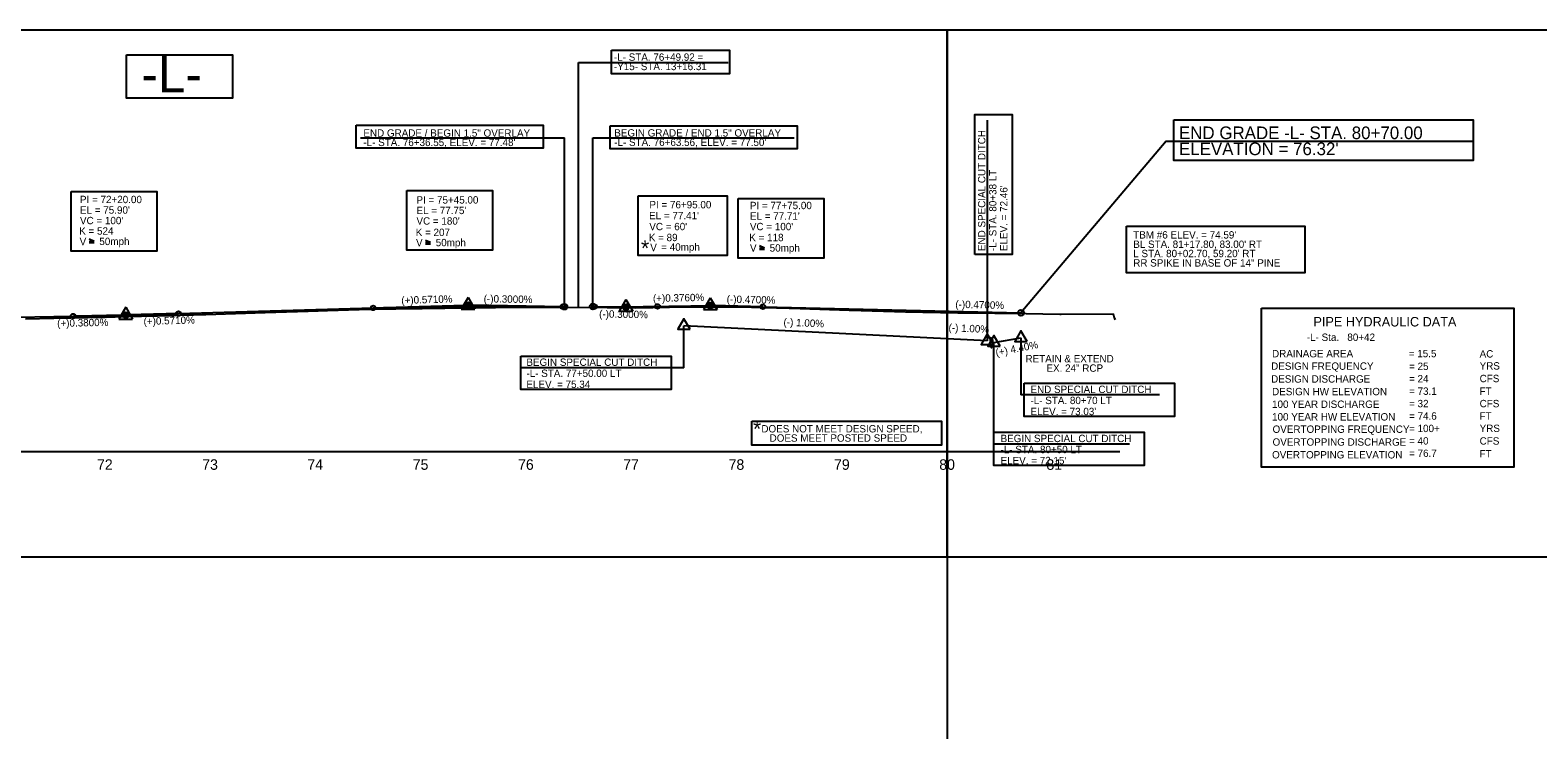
# Model space of a CAD drawing. Extents: x 2366464 to 2375718, y 801842 to 804354.
# Drawn here: x 2373447 to 2374879, y 803581 to 804254 of the extents above; entities that cross this region are included whole.
import ezdxf

# ---------------------------------------------------------------- set-up
doc = ezdxf.new("R2010")
doc.units = 0
for name, color, linetype in [('Default', 7, 'Continuous'), ('Exist Profile Cell', 7, 'Continuous'), ('Exist Vertical Profile Ground Line', 7, 'Continuous'), ('Exist Vertical Profile Horizontal Axis Label Major', 7, 'Continuous'), ('Prop Grid Mask', 7, 'Continuous'), ('Prop PFL VPI Symbol CELL', 7, 'Continuous'), ('Prop Vertical Profile Curve Label', 7, 'Continuous'), ('Prop Vertical Profile Ditch Grade Left', 7, 'Continuous'), ('Prop Vertical Profile Ditch Grade Left Label', 7, 'Continuous'), ('Prop Vertical Profile Grade', 7, 'Continuous'), ('Prop Vertical Profile Grade Label', 7, 'Continuous'), ('Prop VPI Label', 7, 'Continuous'), ('Scratch_Level_5', 7, 'Continuous'), ('Sheet Layout Profile Border Port 1', 7, 'Continuous'), ('Sheet Layout Profile Border Port 2', 7, 'Continuous')]:
    doc.layers.add(name, color=color, linetype=linetype)

# ---------------------------------------------------------------- blocks, each defined once
blk = doc.blocks.new('Profile VPI Symbol')
at = {"layer": 'Prop PFL VPI Symbol CELL'}
for p, q in [((-0.001, 0.147), (-0.13, -0.077)), ((-0.001, 0.147), (0.129, -0.077)), ((-0.13, -0.077), (0.129, -0.077))]:
    blk.add_line(p, q, dxfattribs=at)
for radius in [0.035, 0.024]:
    blk.add_circle((-0.001, -0.003), radius, dxfattribs=at)

msp = doc.modelspace()

# ---------------------------------------------------------------- linework, layer by layer
at = {"layer": 'Default'}
msp.add_line((2374318, 803754), (2374318, 803581), dxfattribs=at)
msp.add_ellipse((2374360, 803957.4), major_axis=(0, 5), ratio=0.2, dxfattribs=at)
at = {"layer": 'Exist Profile Cell'}
msp.add_line((2367318, 803854), (2374481.8, 803854), dxfattribs=at)
at = {"layer": 'Exist Vertical Profile Ground Line'}
msp.add_lwpolyline([(2373442.8, 803980), (2373469.6, 803980.6), (2373518.1, 803981.6), (2373537.6, 803982), (2373552.9, 803982.4), (2373563.2, 803982.6), (2373568.2, 803982.7), (2373583.5, 803983.1), (2373589.9, 803983.3), (2373598.8, 803983.6), (2373602.4, 803983.7), (2373610.6, 803983.9), (2373614.1, 803984.1), (2373670.3, 803986), (2373711.2, 803987.3), (2373720.8, 803987.6), (2373729.4, 803987.8), (2373769.7, 803988.9), (2373770.7, 803988.9), (2373818.3, 803989.8), (2373819.4, 803989.8), (2373862.9, 803990.4), (2373863.9, 803990.4), (2373914, 803991), (2373956.6, 803990.7), (2373967.9, 803991.1), (2374022.4, 803990.4), (2374070.4, 803991.3), (2374071.6, 803991.3), (2374119.1, 803991.2), (2374120.1, 803991.2), (2374167.9, 803990.1), (2374168.4, 803990.1), (2374168.9, 803990.1), (2374225, 803988), (2374225.9, 803988), (2374278.3, 803986.4), (2374327.9, 803985.7), (2374363.2, 803985.3), (2374364.5, 803985.3), (2374375.4, 803985.1), (2374376.7, 803985.1), (2374424.8, 803984.3), (2374426.2, 803984.3), (2374475.6, 803984.5), (2374476.6, 803980.9), (2374477.3, 803979.1)], dxfattribs=at)
at = {"layer": 'Prop Grid Mask'}
for points in [[(2373538.7, 804230.7), (2373639.4, 804230.7), (2373639.4, 804189.4), (2373538.7, 804189.4)], [(2373999.2, 804235.1), (2374111.3, 804235.1), (2374111.3, 804212.5), (2373999.2, 804212.5)], [(2374344.2, 804040.8), (2374344.2, 804173.9), (2374379.6, 804173.9), (2374379.6, 804040.8)], [(2373756.8, 804163.7), (2373934.2, 804163.7), (2373934.2, 804141.8), (2373756.8, 804141.8)], [(2373998, 804163.1), (2374175.4, 804163.1), (2374175.4, 804141.2), (2373998, 804141.2)], [(2374533, 804168.8), (2374817.4, 804168.8), (2374817.4, 804130.2), (2374533, 804130.2)], [(2373805, 804101.7), (2373886.3, 804101.7), (2373886.3, 804045), (2373805, 804045)], [(2373486.2, 804100.7), (2373567.5, 804100.7), (2373567.5, 804044), (2373486.2, 804044)], [(2374024.5, 804096.7), (2374109.1, 804096.7), (2374109.1, 804039.9), (2374024.5, 804039.9)], [(2374119.6, 804094.2), (2374200.9, 804094.2), (2374200.9, 804037.5), (2374119.6, 804037.5)], [(2374488.1, 804067.7), (2374657.6, 804067.7), (2374657.6, 804023.5), (2374488.1, 804023.5)], [(2374616.5, 803990.1), (2374856.1, 803990.1), (2374856.1, 803839.1), (2374616.5, 803839.1)], [(2373913, 803944.5), (2374055.9, 803944.5), (2374055.9, 803912.7), (2373913, 803912.7)], [(2374391, 803918.8), (2374533.8, 803918.8), (2374533.8, 803887), (2374391, 803887)], [(2374132.3, 803882.6), (2374312.5, 803882.6), (2374312.5, 803859.8), (2374132.3, 803859.8)], [(2374362.1, 803872.3), (2374504.9, 803872.3), (2374504.9, 803840.6), (2374362.1, 803840.6)]]:
    msp.add_lwpolyline(points, close=True, dxfattribs=at)
at = {"layer": 'Prop Vertical Profile Curve Label'}
for p, q in [((2373967.9, 803991.1), (2373967.9, 804223.4)), ((2373507.9, 804053.4), (2373503.2, 804055.4)), ((2373503.2, 804053.4), (2373507.9, 804053.4)), ((2373503.2, 804052.3), (2373507.9, 804052.3)), ((2373822.6, 804052.3), (2373827.3, 804052.3)), ((2373822.6, 804051.2), (2373827.3, 804051.2)), ((2373827.3, 804052.3), (2373822.7, 804054.3)), ((2374139.7, 804047.1), (2374144.4, 804047.1)), ((2374139.7, 804046.1), (2374144.4, 804046.1)), ((2374144.4, 804047.1), (2374139.8, 804049.1))]:
    msp.add_line(p, q, dxfattribs=at)
for centre in [(2373588, 803984.9), (2373773, 803990.2), (2373953, 803991.4), (2373983, 803991.5), (2374043, 803991.6), (2374043, 803991.6), (2374143, 803991.3), (2373488, 803982.5)]:
    msp.add_circle(centre, 2.25, dxfattribs=at)
at = {"layer": 'Prop Vertical Profile Ditch Grade Left'}
for p, q in [((2374318, 803960.8), (2374068, 803973.3)), ((2374356, 803958.9), (2374318, 803960.8)), ((2374356, 803960.8), (2374356, 803958.9)), ((2374362.3, 803957.3), (2374388, 803961.7))]:
    msp.add_line(p, q, dxfattribs=at)
at = {"layer": 'Prop Vertical Profile Ditch Grade Left Label'}
for p, q in [((2374356, 804168.5), (2374356, 803958.9)), ((2374356, 804168.5), (2374356, 803958.9)), ((2374356, 804071), (2374356, 803958.9)), ((2374068, 803933.3), (2374068, 803973.3)), ((2374388, 803961.7), (2374388, 803907.6)), ((2374362.3, 803860.9), (2374362.3, 803957.3)), ((2374068, 803933.3), (2373913, 803933.3)), ((2374519.6, 803907.6), (2374388, 803907.6)), ((2374491.1, 803860.9), (2374362.3, 803860.9))]:
    msp.add_line(p, q, dxfattribs=at)
for points in [[(2374073.8, 803969.9), (2374068, 803980), (2374062.1, 803969.9)], [(2374361.8, 803955.5), (2374356, 803965.6), (2374350.1, 803955.5)], [(2374368.1, 803954), (2374362.3, 803964.1), (2374356.4, 803954)], [(2374393.8, 803958.4), (2374388, 803968.5), (2374382.1, 803958.4)]]:
    msp.add_lwpolyline(points, close=True, dxfattribs=at)
at = {"layer": 'Prop Vertical Profile Grade'}
for p, q in [((2373588, 803984.9), (2373773, 803990.2)), ((2373953, 803991.4), (2373954.5, 803991.4)), ((2373981.5, 803991.5), (2373983, 803991.5)), ((2374143, 803991.3), (2374388, 803985.6)), ((2373408, 803981), (2373488, 803982.5))]:
    msp.add_line(p, q, dxfattribs=at)
for points in [[(2373773, 803990.2), (2373776.6, 803990.3), (2373780.2, 803990.4), (2373783.8, 803990.5), (2373787.4, 803990.6), (2373791, 803990.7), (2373794.6, 803990.7), (2373798.2, 803990.8), (2373801.8, 803990.9), (2373805.4, 803991), (2373809, 803991.1), (2373812.6, 803991.1), (2373816.2, 803991.2), (2373819.8, 803991.3), (2373823.4, 803991.3), (2373827, 803991.4), (2373830.6, 803991.4), (2373834.2, 803991.5), (2373837.8, 803991.5), (2373841.4, 803991.6), (2373845, 803991.6), (2373848.6, 803991.7), (2373852.2, 803991.7), (2373855.8, 803991.7), (2373859.4, 803991.8), (2373863, 803991.8), (2373866.6, 803991.8), (2373870.2, 803991.8), (2373873.8, 803991.8), (2373877.4, 803991.8), (2373881, 803991.9), (2373884.6, 803991.9), (2373888.2, 803991.9), (2373891.8, 803991.9), (2373895.4, 803991.9), (2373899, 803991.9), (2373902.6, 803991.9), (2373906.2, 803991.8), (2373909.8, 803991.8), (2373913.4, 803991.8), (2373917, 803991.8), (2373920.6, 803991.8), (2373924.2, 803991.7), (2373927.8, 803991.7), (2373931.4, 803991.7), (2373935, 803991.6), (2373938.6, 803991.6), (2373942.2, 803991.6), (2373945.8, 803991.5), (2373949.4, 803991.5), (2373953, 803991.4)], [(2373983, 803991.5), (2373984.2, 803991.4), (2373985.4, 803991.4), (2373986.6, 803991.4), (2373987.8, 803991.4), (2373989, 803991.4), (2373990.2, 803991.4), (2373991.4, 803991.4), (2373992.6, 803991.3), (2373993.8, 803991.3), (2373995, 803991.3), (2373996.2, 803991.3), (2373997.4, 803991.3), (2373998.6, 803991.3), (2373999.8, 803991.3), (2374001, 803991.3), (2374002.2, 803991.3), (2374003.4, 803991.3), (2374004.6, 803991.3), (2374005.8, 803991.3), (2374007, 803991.3), (2374008.2, 803991.3), (2374009.4, 803991.3), (2374010.6, 803991.3), (2374011.8, 803991.3), (2374013, 803991.3), (2374014.2, 803991.3), (2374015.4, 803991.3), (2374016.6, 803991.3), (2374017.8, 803991.3), (2374019, 803991.3), (2374020.2, 803991.3), (2374021.4, 803991.3), (2374022.6, 803991.3), (2374023.8, 803991.3), (2374025, 803991.3), (2374026.2, 803991.3), (2374027.4, 803991.4), (2374028.6, 803991.4), (2374029.8, 803991.4), (2374031, 803991.4), (2374032.2, 803991.4), (2374033.4, 803991.4), (2374034.6, 803991.4), (2374035.8, 803991.5), (2374037, 803991.5), (2374038.2, 803991.5), (2374039.4, 803991.5), (2374040.6, 803991.5), (2374041.8, 803991.6), (2374043, 803991.6)], [(2374043, 803991.6), (2374045, 803991.6), (2374047, 803991.6), (2374049, 803991.7), (2374051, 803991.7), (2374053, 803991.7), (2374055, 803991.8), (2374057, 803991.8), (2374059, 803991.8), (2374061, 803991.8), (2374063, 803991.9), (2374065, 803991.9), (2374067, 803991.9), (2374069, 803991.9), (2374071, 803991.9), (2374073, 803991.9), (2374075, 803992), (2374077, 803992), (2374079, 803992), (2374081, 803992), (2374083, 803992), (2374085, 803992), (2374087, 803992), (2374089, 803992), (2374091, 803992), (2374093, 803992), (2374095, 803992), (2374097, 803992), (2374099, 803992), (2374101, 803992), (2374103, 803991.9), (2374105, 803991.9), (2374107, 803991.9), (2374109, 803991.9), (2374111, 803991.9), (2374113, 803991.9), (2374115, 803991.8), (2374117, 803991.8), (2374119, 803991.8), (2374121, 803991.8), (2374123, 803991.7), (2374125, 803991.7), (2374127, 803991.7), (2374129, 803991.6), (2374131, 803991.6), (2374133, 803991.6), (2374135, 803991.5), (2374137, 803991.5), (2374139, 803991.4), (2374141, 803991.4), (2374143, 803991.3)], [(2373488, 803982.5), (2373490, 803982.6), (2373492, 803982.6), (2373494, 803982.6), (2373496, 803982.7), (2373498, 803982.7), (2373500, 803982.8), (2373502, 803982.8), (2373504, 803982.8), (2373506, 803982.9), (2373508, 803982.9), (2373510, 803983), (2373512, 803983), (2373514, 803983.1), (2373516, 803983.1), (2373518, 803983.1), (2373520, 803983.2), (2373522, 803983.2), (2373524, 803983.3), (2373526, 803983.3), (2373528, 803983.4), (2373530, 803983.4), (2373532, 803983.5), (2373534, 803983.5), (2373536, 803983.6), (2373538, 803983.6), (2373540, 803983.6), (2373542, 803983.7), (2373544, 803983.7), (2373546, 803983.8), (2373548, 803983.8), (2373550, 803983.9), (2373552, 803983.9), (2373554, 803984), (2373556, 803984), (2373558, 803984.1), (2373560, 803984.1), (2373562, 803984.2), (2373564, 803984.2), (2373566, 803984.3), (2373568, 803984.4), (2373570, 803984.4), (2373572, 803984.5), (2373574, 803984.5), (2373576, 803984.6), (2373578, 803984.6), (2373580, 803984.7), (2373582, 803984.7), (2373584, 803984.8), (2373586, 803984.8), (2373588, 803984.9)]]:
    msp.add_spline(points, degree=3, dxfattribs=at)
at = {"layer": 'Prop VPI Label'}
for p, q in [((2373967.9, 804223.4), (2374109.9, 804223.4)), ((2373760.9, 804151.7), (2373954.5, 804151.7)), ((2373954.5, 803991.4), (2373954.5, 804151.7)), ((2373981.5, 803991.5), (2373981.5, 804151.7)), ((2373981.5, 804151.7), (2374172.6, 804151.7)), ((2374526, 804148.5), (2374388, 803985.6)), ((2374526, 804148.5), (2374816.8, 804148.5)), ((2373773, 803990.2), (2373860.2, 803992.7)), ((2373953, 803991.4), (2373865.7, 803992.7)), ((2373983, 803991.5), (2374010.2, 803991.1)), ((2374043, 803991.6), (2374015.7, 803991.1)), ((2374043, 803991.6), (2374090.2, 803992.5)), ((2374143, 803991.3), (2374095.7, 803992.5)), ((2373488, 803982.5), (2373535.2, 803983.4)), ((2373588, 803984.9), (2373540.7, 803983.6))]:
    msp.add_line(p, q, dxfattribs=at)
for centre in [(2373863, 803992.8), (2373954.5, 803991.4), (2373981.5, 803991.5), (2374013, 803991), (2374093, 803992.5), (2374388, 803985.6), (2374388, 803985.6), (2373538, 803983.5)]:
    msp.add_circle(centre, 2.75, dxfattribs=at)
at = {"layer": 'Scratch_Level_5'}
for p, q in [((2373718, 803988.6), (2373718, 803988.6)), ((2373768, 803989.4), (2373768, 803989.4)), ((2373834, 803990.7), (2373834, 803990.7)), ((2373918, 803991.7), (2373918, 803991.7)), ((2373918, 803991.7), (2373918, 803991.7)), ((2373954.5, 803991.4), (2373954.5, 803991.4)), ((2373981.5, 803991.5), (2373981.5, 803991.5)), ((2374068, 803991.9), (2374068, 803991.9)), ((2374168, 803990.7), (2374168, 803990.7)), ((2374268, 803987.7), (2374268, 803987.7)), ((2373468, 803981.2), (2373468, 803981.2)), ((2373518, 803982.2), (2373518, 803982.2)), ((2373579, 803984), (2373579, 803984)), ((2373637, 803985.2), (2373637, 803985.2)), ((2374368, 803985.9), (2374368, 803985.9))]:
    msp.add_line(p, q, dxfattribs=at)
at = {"layer": 'Sheet Layout Profile Border Port 1'}
msp.add_lwpolyline([(2372918, 803754), (2374318, 803754), (2374318, 804254), (2372918, 804254)], close=True, dxfattribs=at)
at = {"layer": 'Sheet Layout Profile Border Port 2'}
msp.add_lwpolyline([(2374318, 803754), (2375718, 803754), (2375718, 804254), (2374318, 804254)], close=True, dxfattribs=at)

# ---------------------------------------------------------------- block references
at = {"layer": 'Prop Grid Mask', "xscale": 50, "yscale": 50}
for p in [(2373538, 803983.5), (2373863, 803992.8), (2374013, 803991), (2374093, 803992.5)]:
    msp.add_blockref('Profile VPI Symbol', p, dxfattribs=at)

# ---------------------------------------------------------------- texts
at = {"layer": 'Default'}
for s, p in [('RETAIN & EXTEND', (2374392.3, 803938.5)), ('EX. 24" RCP', (2374412.2, 803929.6))]:
    msp.add_text(s, height=7, dxfattribs=at).set_placement(p)
at = {"layer": 'Exist Vertical Profile Horizontal Axis Label Major'}
for s, p in [('72', (2373510.7, 803836.5)), ('73', (2373610.6, 803836.5)), ('74', (2373710.4, 803836.5)), ('75', (2373810.5, 803836.5)), ('76', (2373910.5, 803836.5)), ('77', (2374010.3, 803836.5)), ('78', (2374110.4, 803836.5)), ('79', (2374210.5, 803836.5)), ('80', (2374310.4, 803836.5)), ('81', (2374412.2, 803836.5))]:
    msp.add_text(s, height=10, dxfattribs=at).set_placement(p)
at = {"layer": 'Prop Vertical Profile Curve Label'}
for s, height, p in [('-L- STA. 76+49.92 = ', 7, (2374001.5, 804224.9)), ('-Y15- STA. 13+16.31', 7, (2374001.5, 804216)), ("VC = 100'", 7, (2373494.5, 804069.7)), ("VC = 180'", 7, (2373814, 804069.3)), ('K = 524', 7, (2373493.8, 804059.8)), ('K = 207', 7, (2373813.3, 804058.5)), ("VC = 60'", 7, (2374035.1, 804064)), ('K = 89', 7, (2374034.6, 804053.6)), ("VC = 100'", 7, (2374130.6, 804064)), ('K = 118', 7, (2374130, 804053.6)), ('V', 7, (2373494.2, 804049.8)), ('50mph', 7, (2373512.9, 804049.9)), ('V', 7, (2373813.6, 804048.7)), ('50mph', 7, (2373832.3, 804048.8)), ('*', 15, (2374027.2, 804039.5)), ('V', 7, (2374036, 804044.1)), ('= 40mph', 7, (2374046.4, 804044.5)), ('V', 7, (2374130.7, 804043.6)), ('50mph', 7, (2374149.4, 804043.7)), ('*', 15, (2374133.6, 803867.9)), ('DOES NOT MEET DESIGN SPEED, ', 7, (2374141.5, 803872)), ('   DOES MEET POSTED SPEED', 7, (2374141.5, 803863.2))]:
    msp.add_text(s, height=height, dxfattribs=at).set_placement(p)
at = {"layer": 'Prop Vertical Profile Ditch Grade Left Label'}
for s, rotation, p in [('END SPECIAL CUT DITCH', 90, (2374354.2, 804044.2)), ('-L- STA. 80+38 LT', 90, (2374364.7, 804044.2)), ("ELEV. = 72.46'", 90, (2374375.2, 804044.2)), ('(-) 1.00%', 357.2828, (2374162.4, 803973.5)), ('(-) 1.00%', 357.2828, (2374319.1, 803968.2)), ('(+) 4.40%', 11.1463, (2374364.6, 803944.3))]:
    msp.add_text(s, height=7, rotation=rotation, dxfattribs=at).set_placement(p)
for s, height, p in [('PIPE HYDRAULIC DATA', 9, (2374665.7, 803972.6)), ('-L- Sta.   80+42', 7, (2374659.4, 803958.9)), ('DRAINAGE AREA', 7, (2374626.4, 803943.3)), ('= 15.5', 7, (2374756.2, 803943.4)), ('AC', 7, (2374823.5, 803943.1)), ('-L- STA. 77+50.00 LT', 7, (2373918.4, 803924.7)), ('BEGIN SPECIAL CUT DITCH', 7, (2373918.4, 803935.2)), ('DESIGN FREQUENCY', 7, (2374625.5, 803931.5)), ('= 25', 7, (2374756.5, 803931.3)), ('YRS', 7, (2374823.5, 803931.7)), ('ELEV. = 75.34', 7, (2373918.4, 803914.2)), ('END SPECIAL CUT DITCH', 7, (2374397, 803909.4)), ('DESIGN DISCHARGE', 7, (2374625.5, 803919.3)), ('= 24', 7, (2374756.5, 803919.5)), ('CFS', 7, (2374823.5, 803919.7)), ('-L- STA. 80+70 LT', 7, (2374397, 803898.9)), ('DESIGN HW ELEVATION', 7, (2374626.4, 803907.3)), ('100 YEAR DISCHARGE', 7, (2374626.4, 803895.3)), ('= 73.1', 7, (2374756.5, 803907.7)), ('= 32', 7, (2374756.5, 803895.9)), ('CFS', 7, (2374823.5, 803895.9)), ('FT', 7, (2374823.5, 803907.7)), ("ELEV. = 73.03'", 7, (2374397, 803888.4)), ('100 YEAR HW ELEVATION', 7, (2374626.4, 803883.3)), ('= 74.6', 7, (2374756.5, 803884.1)), ('FT', 7, (2374823.5, 803884.1)), ('OVERTOPPING FREQUENCY', 7, (2374626.9, 803871.6)), ('= 100+', 7, (2374756.5, 803872.3)), ('YRS', 7, (2374823.5, 803872.4)), ('-L- STA. 80+50 LT', 7, (2374368.6, 803852.3)), ('BEGIN SPECIAL CUT DITCH', 7, (2374368.6, 803862.8)), ('OVERTOPPING DISCHARGE', 7, (2374626.9, 803859.4)), ('= 40', 7, (2374756.5, 803860.5)), ('CFS', 7, (2374823.5, 803860.4)), ("ELEV. = 72.15'", 7, (2374368.6, 803841.8)), ('OVERTOPPING ELEVATION', 7, (2374626.4, 803847.3)), ('= 76.7', 7, (2374756.5, 803848.7)), ('FT', 7, (2374823.5, 803848.3))]:
    msp.add_text(s, height=height, dxfattribs=at).set_placement(p)
at = {"layer": 'Prop Vertical Profile Grade Label'}
for s, rotation, p in [('(+)0.5710%', 1.6353, (2373799.7, 803994)), ('(-)0.3000%', 359.1406, (2373877.8, 803995.5)), ('(+)0.3760%', 1.0771, (2374038.6, 803995.9)), ('(-)0.4700%', 358.6538, (2374108.5, 803995.2)), ('(-)0.3000%', 359.1406, (2373987.4, 803981.1)), ('(-)0.4700%', 358.6538, (2374325.6, 803990.3)), ('(+)0.3800%', 1.0885, (2373472.9, 803972.2)), ('(+)0.5710%', 1.6353, (2373555, 803974))]:
    msp.add_text(s, height=7, rotation=rotation, dxfattribs=at).set_placement(p)
at = {"layer": 'Prop VPI Label'}
for s, height, p in [('-L-', 35, (2373553, 804194.8)), ('BEGIN GRADE / END 1.5" OVERLAY', 7, (2374001.8, 804152.9)), ('END GRADE -L- STA. 80+70.00', 12, (2374538, 804150.5)), ("-L- STA. 76+63.56, ELEV. = 77.50'", 7, (2374001.8, 804144)), ("ELEVATION = 76.32'", 12, (2374538, 804135.3)), ('PI = 72+20.00', 7, (2373494.5, 804089.7)), ('PI = 75+45.00', 7, (2373814, 804089.3)), ('PI = 76+95.00', 7, (2374035.2, 804084.8)), ('PI = 77+75.00', 7, (2374130.6, 804084)), ("EL = 75.90'", 7, (2373494.5, 804079.7)), ("EL = 77.75'", 7, (2373814, 804079.3)), ("EL = 77.41'", 7, (2374034.9, 804074.4)), ("EL = 77.71'", 7, (2374130.6, 804074)), ("TBM #6 ELEV. = 74.59'", 7, (2374494.6, 804056.1)), ("BL STA. 81+17.80, 83.00' RT", 7, (2374494.6, 804047.2)), ("L STA. 80+02.70, 59.20' RT", 7, (2374494.6, 804038.4)), ('RR SPIKE IN BASE OF 14" PINE', 7, (2374494.6, 804029.5))]:
    msp.add_text(s, height=height, dxfattribs=at).set_placement(p)
for s, p in [('END GRADE / BEGIN 1.5" OVERLAY', (2373763.6, 804152.8)), ("-L- STA. 76+36.55, ELEV. = 77.48'", (2373763.6, 804143.9))]:
    msp.add_text(s, height=7, rotation=360, dxfattribs=at).set_placement(p)

doc.saveas('drawing.dxf')
